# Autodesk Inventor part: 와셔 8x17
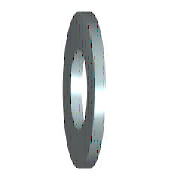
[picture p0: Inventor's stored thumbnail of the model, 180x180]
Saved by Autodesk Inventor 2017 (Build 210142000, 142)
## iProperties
Created: 2012-02
Part Number: 와셔 8x17
Material: 강철, 연강
Description: 평면 와셔
Document SubType Name: Modeling
Standard: KS B 1326
Designer: mduedu
Standards Organization: KS
Language: ko-KR
Size Designation: 8x17
Categories: <MemberInstance><Categories><Category DisplayName="조임쇠" InternalName="e4da775c-781d-43d5-af7c-5136215cf5a6" Mnemonic="FSTN"><Category DisplayName="와셔" InternalN
Density: 1 g/cm^3
Appearance: 파란색 - 벽 페인트 - 광택
IsCustomPart: 1
Author: mduedu
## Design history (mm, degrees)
sketch "스케치"
  geometry: C1 r 8.5 at (0, 0); C2 r 4.5 at (0, 0); 1 further point
  constraints: 2 centre point, 2 coincident
  dimensions: "d0" = 9 diameter of C2 (= SD1); "d1" = 17 diameter of C1 (= SD2)
extrude "본체" new body sketch "스케치" distance "d2" = 1.6 (= SD); taper "d3" = 0 deg
workaxis "Work Axis1"
workplane "Work Plane1"
body "Solid1"
other parameters: "SD1" = 9 [user parameter; used in 1 equation term], "SD2" = 17 [user parameter; used in 1 equation term], "SD" = 1.6 [user parameter; used in 1 equation term], "d4" = 0, "d5" = 0, "d6" = 0, "d7" = 0, "NND" = 8 [user parameter]
